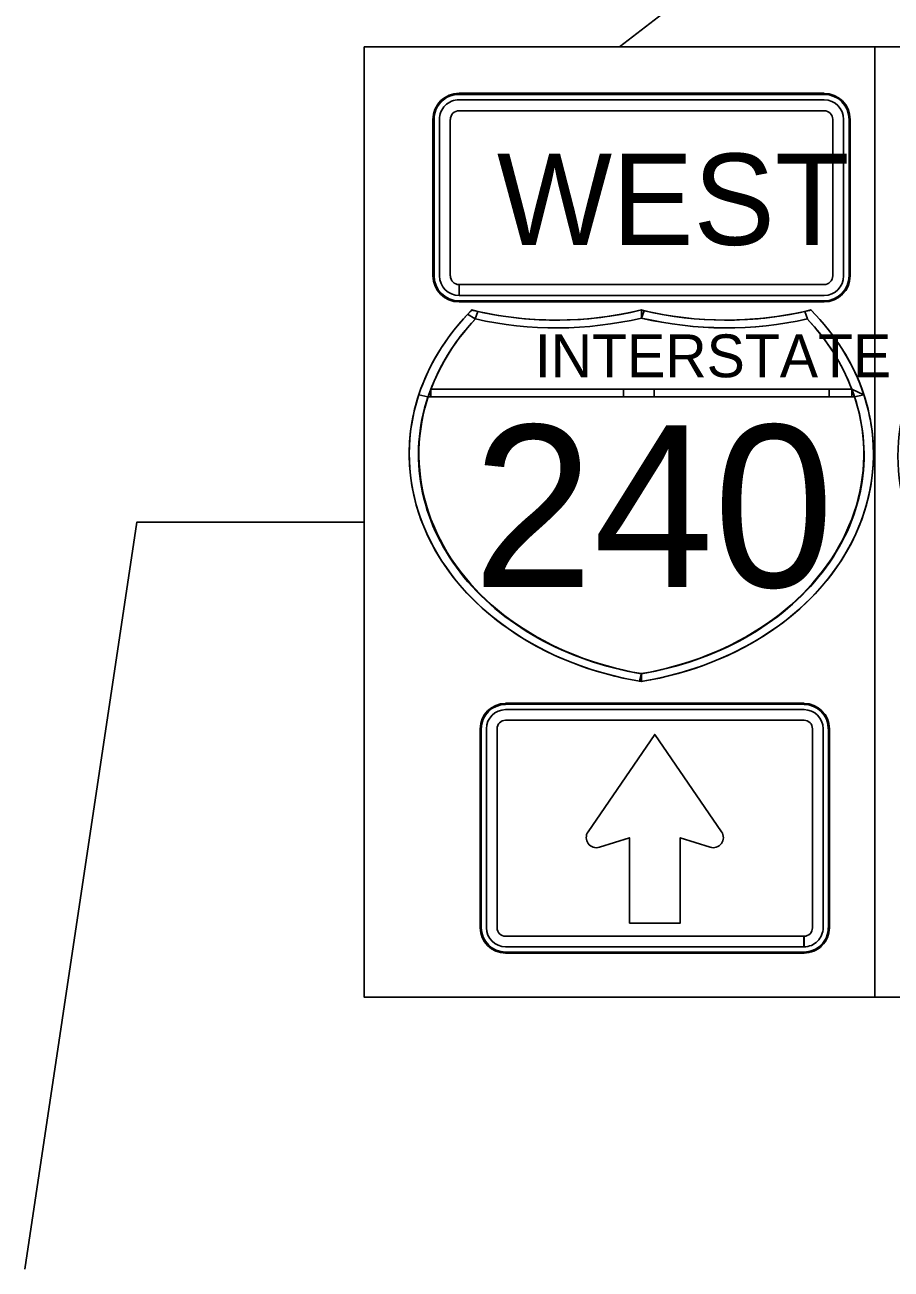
# Model space of a CAD drawing. Extents: x 886234 to 968767, y 455416 to 684046.
# Drawn here: x 916643 to 917474, y 470155 to 471348 of the extents above; entities that cross this region are included whole.
import ezdxf

# ---------------------------------------------------------------- set-up
doc = ezdxf.new("R2010")
doc.units = 0
for name, color, linetype in [('TC CONSTRUCTION PROPOSED ROADWAY SHADE', 7, 'Continuous'), ('TC DEV SIGN BLACK 239', 7, 'Continuous'), ('TC DEV SIGN BLACK ZERO', 7, 'Continuous'), ('TC DEV SIGN WHITE', 7, 'Continuous'), ('TC LABEL TEXT', 7, 'Continuous')]:
    doc.layers.add(name, color=color, linetype=linetype)

msp = doc.modelspace()

# ---------------------------------------------------------------- linework, layer by layer
at = {"layer": 'TC CONSTRUCTION PROPOSED ROADWAY SHADE'}
msp.add_lwpolyline([(916968.6, 471326.7), (917458.4, 471326.7), (917458.4, 470415.7), (916968.6, 470415.7)], close=True, dxfattribs=at)
at = {"layer": 'TC DEV SIGN BLACK 239'}
for p, q in [((917409.7, 471275.9), (917059.7, 471275.9)), ((917040.9, 471257.2), (917040.9, 471107.2)), ((917051.3, 471257.2), (917051.3, 471107.2)), ((917409.7, 471265.5), (917059.7, 471265.5)), ((917418.1, 471107.2), (917418.1, 471257.2)), ((917428.5, 471107.2), (917428.5, 471257.2)), ((917059.7, 471088.4), (917059.7, 471098.8)), ((917059.8, 471098.8), (917409.7, 471098.8)), ((917059.8, 471098.8), (917059.8, 471088.4)), ((917059.8, 471088.4), (917409.7, 471088.4)), ((917104.3, 470691.3), (917390.5, 470691.3)), ((917086.1, 470482.2), (917086.1, 470673)), ((917096.2, 470482.2), (917096.2, 470673)), ((917104.3, 470681.1), (917390.5, 470681.1)), ((917398.6, 470673), (917398.7, 470482.2)), ((917408.8, 470673), (917408.8, 470482.2)), ((917390.4, 470474.1), (917104.3, 470474.1)), ((917390.4, 470474.1), (917390.4, 470463.9)), ((917390.5, 470463.9), (917390.5, 470474.1)), ((917390.4, 470463.9), (917104.3, 470463.9))]:
    msp.add_line(p, q, dxfattribs=at)
for points in [[(917183.4, 470574.2), (917247.4, 470667.5), (917311.4, 470574.2)], [(917183.4, 470574.2), (917247.4, 470667.5), (917311.4, 470574.2)], [(917183.4, 470574.2), (917247.4, 470667.5), (917311.4, 470574.2)], [(917223.1, 470486.7), (917223.1, 470568.5), (917194.3, 470559.4)], [(917223.1, 470486.7), (917223.1, 470568.5), (917194.3, 470559.4)], [(917223.1, 470486.7), (917223.1, 470568.5), (917194.3, 470559.4)], [(917300.5, 470559.4), (917271.8, 470568.5), (917271.8, 470486.7), (917223.1, 470486.7)], [(917300.5, 470559.4), (917271.8, 470568.5), (917271.8, 470486.7), (917223.1, 470486.7)], [(917300.5, 470559.4), (917271.8, 470568.5), (917271.8, 470486.7), (917223.1, 470486.7)]]:
    msp.add_lwpolyline(points, dxfattribs=at)
for centre, start, end in [((917191.4, 470568.7), 145.5508, 287.601), ((917191.4, 470568.7), 145.5508, 287.601), ((917191.4, 470568.7), 145.5508, 287.601), ((917303.4, 470568.7), 252.399, 34.4492), ((917303.4, 470568.7), 252.399, 34.4492), ((917303.4, 470568.7), 252.399, 34.4492)]:
    msp.add_arc(centre, 9.74, start, end, dxfattribs=at)
for centre, major_axis, start_param, end_param in [((917059.7, 471257.2), (18.8, 0), 1.570796, 3.141593), ((917409.7, 471257.2), (18.8, 0), 0, 1.570796), ((917059.7, 471257.2), (8.33, 0), 1.570796, 3.141593), ((917409.7, 471257.2), (8.33, 0), 0, 1.570796), ((917059.7, 471107.2), (18.8, 0), 3.141593, 4.712389), ((917059.7, 471107.2), (8.33, 0), 3.141593, 4.712389), ((917409.7, 471107.2), (18.8, 0), 4.712389, 6.283185), ((917409.7, 471107.2), (8.33, 0), 4.712389, 6.283185), ((917104.3, 470673), (-18.3, 0), 4.712389, 6.283185), ((917390.5, 470673), (-18.3, 0), 3.141593, 4.712389), ((917104.3, 470673), (-8.11, 0), 4.712389, 6.283185), ((917390.5, 470673), (-8.11, 0), 3.141593, 4.712389), ((917104.3, 470482.2), (-18.3, 0), 0, 1.570796), ((917104.3, 470482.2), (-8.11, 0), 0, 1.570796), ((917390.5, 470482.2), (-18.3, 0), 1.570796, 3.141593), ((917390.5, 470482.2), (-8.11, 0), 1.570796, 3.141593)]:
    msp.add_ellipse(centre, major_axis=major_axis, ratio=0.999865, start_param=start_param, end_param=end_param, dxfattribs=at)
at = {"layer": 'TC DEV SIGN BLACK ZERO'}
for p, q in [((917409.7, 471282.2), (917059.7, 471282.2)), ((917059.7, 471281.1), (917059.7, 471281.1)), ((917409.7, 471281.1), (917059.7, 471281.1)), ((917409.7, 471281.1), (917409.7, 471281.1)), ((917034.7, 471257.2), (917034.7, 471107.2)), ((917035.7, 471257.2), (917035.7, 471107.2)), ((917035.7, 471257.2), (917035.7, 471257.2)), ((917433.7, 471257.2), (917433.7, 471257.2)), ((917433.7, 471107.2), (917433.7, 471257.2)), ((917434.7, 471107.2), (917434.7, 471257.2)), ((917035.7, 471107.2), (917035.7, 471107.2)), ((917433.7, 471107.2), (917433.7, 471107.2)), ((917059.7, 471082.2), (917059.7, 471083.2)), ((917059.7, 471083.2), (917059.7, 471083.2)), ((917059.7, 471083.2), (917409.7, 471083.2)), ((917059.7, 471083.2), (917059.7, 471082.2)), ((917059.7, 471082.2), (917409.7, 471082.2)), ((917409.7, 471083.2), (917409.7, 471083.2)), ((917075.3, 471065.9), (917077.8, 471073.1)), ((917234.7, 471066.7), (917234.5, 471074.5)), ((917234.7, 471067.3), (917234.5, 471074.5)), ((917391.2, 471073.1), (917393.7, 471065.9)), ((917032.6, 470998.5), (917436.4, 470998.5)), ((917217.5, 470998.5), (917032.6, 470998.5)), ((917246.8, 470998.5), (917217.5, 470998.5)), ((917414.6, 470998.5), (917246.8, 470998.5)), ((917436.4, 470998.5), (917414.6, 470998.5)), ((917448, 470993), (917436.4, 470998.5)), ((917029.9, 470991.1), (917439, 470991.1)), ((917029.9, 470991.1), (917032.6, 470991.1)), ((917032.6, 470991.1), (917217.5, 470991.1)), ((917217.5, 470991.1), (917246.8, 470991.1)), ((917246.8, 470991.1), (917414.6, 470991.1)), ((917414.6, 470991.1), (917436.4, 470991.1)), ((917438.9, 470991.6), (917436.4, 470991.1)), ((917436.4, 470991.1), (917439, 470991.1)), ((917011.8, 470937.5), (917011.8, 470935.3)), ((917457.1, 470935.2), (917457.1, 470937.6)), ((917234.5, 470718.2), (917234.5, 470725.8)), ((917104.3, 470697.4), (917390.5, 470697.4)), ((917104.3, 470696.3), (917390.5, 470696.4)), ((917104.3, 470696.3), (917104.3, 470696.3)), ((917390.5, 470696.3), (917390.5, 470696.4)), ((917080, 470482.2), (917080, 470673)), ((917081, 470673), (917081, 470673)), ((917081, 470482.2), (917081, 470673)), ((917413.9, 470673), (917413.9, 470482.2)), ((917413.9, 470673), (917413.9, 470673)), ((917414.9, 470673), (917414.9, 470482.2)), ((917081, 470482.2), (917081, 470482.2)), ((917413.9, 470482.2), (917413.9, 470482.2)), ((917104.3, 470458.9), (917104.3, 470458.9)), ((917390.5, 470458.9), (917104.3, 470458.9)), ((917390.5, 470457.8), (917104.3, 470457.8)), ((917390.5, 470457.8), (917390.5, 470458.9)), ((917390.5, 470458.9), (917390.5, 470458.9)), ((917390.5, 470458.9), (917390.5, 470457.8))]:
    msp.add_line(p, q, dxfattribs=at)
for points in [[(917067.9, 471070.4), (917075.3, 471065.9)], [(917075.3, 471065.9), (917067.9, 471070.4)], [(917071.8, 471074.5), (917071.8, 471074.5), (917071.8, 471074.5)], [(917077.8, 471073.1), (917075.3, 471065.9)], [(917234.5, 471066.7), (917234.7, 471067.3)], [(917234.7, 471074.4), (917234.7, 471067.3), (917237.3, 471073.8)], [(917237.3, 471073.8), (917234.7, 471066.7)], [(917393.7, 471065.9), (917391.2, 471073.1)], [(917397.2, 471074.5), (917397.2, 471074.5), (917397.1, 471074.5)], [(917032.6, 470998.5), (917032.6, 470991.1)], [(917032.6, 470991.1), (917032.6, 470998.5)], [(917217.5, 470991.1), (917217.5, 470998.5)], [(917217.5, 470998.5), (917217.5, 470991.1)], [(917246.8, 470998.5), (917246.8, 470991.1)], [(917246.8, 470991.1), (917246.8, 470998.5)], [(917414.6, 470991.1), (917414.6, 470998.5)], [(917414.6, 470998.5), (917414.6, 470991.1)], [(917436.4, 470998.5), (917448, 470993)], [(917436.4, 470991.1), (917436.4, 470998.5)], [(917436.4, 470998.5), (917436.4, 470991.1), (917438.9, 470991.6), (917436.4, 470998.5)], [(917021, 470993), (917029.9, 470991.1)], [(917029.9, 470991.1), (917021, 470993)], [(917439, 470991.1), (917438.9, 470991.6)], [(917448, 470993), (917439, 470991.1)], [(917439, 470991.1), (917448, 470993)], [(917232.6, 470718.5), (917234.5, 470725.8)], [(917234.5, 470725.8), (917232.6, 470718.5), (917234.5, 470718.2)], [(917234.5, 470725.8), (917234.5, 470718.2)]]:
    msp.add_lwpolyline(points, dxfattribs=at)
for centre, major_axis, ratio, start_param, end_param in [((917059.7, 471257.2), (25, 0), 0.999865, 1.570796, 3.141593), ((917059.7, 471257.2), (24, 0), 0.999865, 1.570796, 3.141593), ((917409.7, 471257.2), (25, 0), 0.999865, 0, 1.570796), ((917409.7, 471257.2), (24, 0), 0.999865, 0, 1.570796), ((917059.7, 471107.2), (25, 0), 0.999865, 3.141593, 4.712389), ((917059.7, 471107.2), (24, 0), 0.999865, 3.141593, 4.712389), ((917409.7, 471107.2), (25, 0), 0.999865, 4.712389, 6.283185), ((917409.7, 471107.2), (24, 0), 0.999865, 4.712389, 6.283185), ((917290.2, 470936.4), (-278.3, 0), 0.800002, 5.614188, 7.652625), ((917290.2, 470936.4), (-269, 0), 0.800002, 5.637358, 7.64558), ((917290.2, 470936.4), (-278.3, 0), 0.800002, 5.637358, 6.026219), ((917290.2, 470936.4), (-269, 0), 0.800002, 5.637358, 6.026219), ((917290.2, 470936.4), (-278.3, 0), 0.800002, 5.614216, 5.637358), ((917153.2, 471287.4), (278.3, 0), 0.800002, 4.415792, 5.008922), ((917153.2, 471287.4), (278.3, 0), 0.800002, 4.415856, 4.438209), ((917153.2, 471287.4), (287.6, 0), 0.800002, 4.438209, 4.999074), ((917153.2, 471287.4), (287.6, 0), 0.800002, 4.438209, 4.999074), ((917153.2, 471287.4), (278.3, 0), 0.800002, 4.438209, 5.008909), ((917315.8, 471287.4), (278.3, 0), 0.800002, 4.415856, 5.008986), ((917178.8, 470936.4), (278.3, 0), 0.800002, 4.913746, 6.952183), ((917315.8, 471287.4), (287.6, 0), 0.800002, 4.425704, 4.986569), ((917178.8, 470936.4), (269, 0), 0.800002, 4.920791, 6.929013), ((917315.8, 471287.4), (278.3, 0), 0.800002, 4.416709, 4.426515), ((917315.9, 471287.1), (287.2, 0), 0.800002, 4.425686, 4.986568), ((917315.8, 471287.4), (278.3, 0), 0.800002, 4.426515, 4.986569), ((917315.8, 471287.4), (278.3, 0), 0.800002, 4.986569, 5.008922), ((917178.8, 470936.4), (269, 0), 0.800002, 0.292795, 0.645828), ((917178.8, 470936.4), (278.3, 0), 0.800002, 0.256966, 0.66897), ((917758.8, 470933.9), (-278.3, 0), 0.800002, 5.614188, 7.652625), ((917290.2, 470936.4), (-269, 0), 0.800002, 5.99039, 6.026219), ((917178.8, 470936.4), (269, 0), 0.800002, 0.256966, 0.292795), ((917288.8, 470935.7), (-268, 0), 0.800002, 6.022151, 7.649781), ((917290.2, 470936.4), (-278.3, 0), 0.800002, 6.026219, 6.278259), ((917180.1, 470935.7), (268, 0), 0.800002, 4.916934, 6.544356), ((917178.8, 470936.4), (278.3, 0), 0.800002, 0.005231, 0.256966), ((917290.2, 470936.4), (-278.3, 0), 0.800002, 0.004927, 1.362388), ((917178.8, 470936.4), (278.3, 0), 0.800002, 4.913748, 6.277955), ((917178.8, 470936.4), (269, 0), 0.800002, 4.920791, 4.921138), ((917290.2, 470936.4), (-278.3, 0), 0.800002, 1.36935, 1.369438), ((917178.8, 470936.4), (278.3, 0), 0.800002, 4.913747, 4.913748), ((917104.3, 470673), (-24.3, 0), 0.999865, 4.712389, 6.283185), ((917104.3, 470673), (-23.3, 0), 0.999865, 4.712389, 6.283185), ((917390.5, 470673), (-24.3, 0), 0.999865, 3.141593, 4.712389), ((917390.5, 470673), (-23.3, 0), 0.999865, 3.141593, 4.712389), ((917104.3, 470482.2), (-24.3, 0), 0.999865, 0, 1.570796), ((917104.3, 470482.2), (-23.3, 0), 0.999865, 0, 1.570796), ((917390.5, 470482.2), (-24.3, 0), 0.999865, 1.570796, 3.141593), ((917390.5, 470482.2), (-23.3, 0), 0.999865, 1.570796, 3.141593)]:
    msp.add_ellipse(centre, major_axis=major_axis, ratio=ratio, start_param=start_param, end_param=end_param, dxfattribs=at)
at = {"layer": 'TC DEV SIGN WHITE'}
for p, q in [((917409.7, 471282.2), (917059.7, 471282.2)), ((917034.7, 471257.2), (917034.7, 471107.2)), ((917434.7, 471107.2), (917434.7, 471257.2)), ((917059.7, 471082.2), (917409.7, 471082.2)), ((917104.3, 470697.4), (917390.5, 470697.4)), ((917080, 470482.2), (917080, 470673)), ((917414.9, 470673), (917414.9, 470482.2)), ((917390.5, 470457.8), (917104.3, 470457.8))]:
    msp.add_line(p, q, dxfattribs=at)
for centre, major_axis, start_param, end_param in [((917059.7, 471257.2), (25, 0), 1.570796, 3.141593), ((917409.7, 471257.2), (25, 0), 0, 1.570796), ((917059.7, 471107.2), (25, 0), 3.141593, 4.712389), ((917409.7, 471107.2), (25, 0), 4.712389, 6.283185), ((917104.3, 470673), (-24.3, 0), 4.712389, 6.283185), ((917390.5, 470673), (-24.3, 0), 3.141593, 4.712389), ((917104.3, 470482.2), (-24.3, 0), 0, 1.570796), ((917390.5, 470482.2), (-24.3, 0), 1.570796, 3.141593)]:
    msp.add_ellipse(centre, major_axis=major_axis, ratio=0.999865, start_param=start_param, end_param=end_param, dxfattribs=at)
at = {"layer": 'TC LABEL TEXT'}
msp.add_line((918429.9, 472267.5), (917213.5, 471326.7), dxfattribs=at)
for points in [[(916968.6, 471326.7), (917458.4, 471326.7), (917458.4, 470415.7), (916968.6, 470415.7)], [(917458.4, 471326.7), (917948.1, 471326.7), (917948.1, 470415.7), (917458.4, 470415.7)]]:
    msp.add_lwpolyline(points, close=True, dxfattribs=at)
msp.add_lwpolyline([(916968.6, 470871.2), (916750.6, 470871), (916643.3, 470154.9)], dxfattribs=at)

# ---------------------------------------------------------------- texts
at = {"layer": 'TC DEV SIGN BLACK 239'}
msp.add_text('WEST', height=87.5, rotation=360, dxfattribs=at).set_placement((917096, 471136.9))
at = {"layer": 'TC DEV SIGN BLACK ZERO'}
for s, height, p in [('INTERSTATE', 41.06, (917132.4, 471010)), ('240', 155.13, (917073, 470808.9))]:
    msp.add_text(s, height=height, rotation=360, dxfattribs=at).set_placement(p)

doc.saveas('drawing.dxf')
